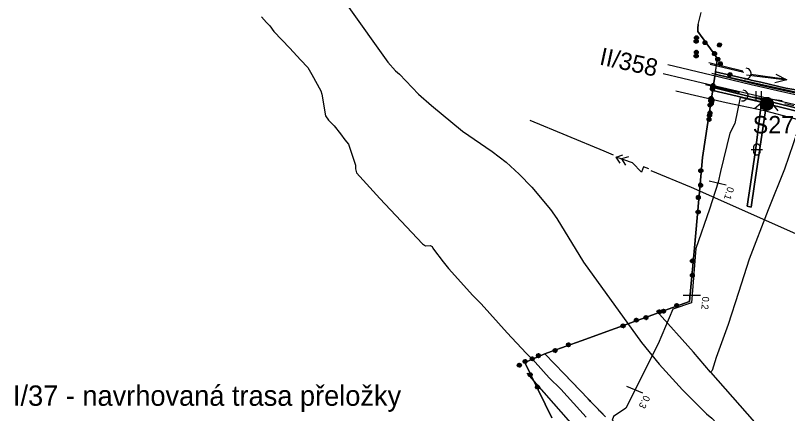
# Model space of a CAD drawing. Extents: x -645676 to -642474, y -1077513 to -1072613.
# Drawn here: x -645676 to -645011, y -1074580 to -1074237 of the extents above; entities that cross this region are included whole.
import ezdxf

# ---------------------------------------------------------------- set-up
doc = ezdxf.new("R2010")
doc.units = 0
for name, color, linetype in [('_elezni_n__tra_', 7, 'Continuous'), ('ELEKTRO', 7, 'Continuous'), ('Kanalizace', 7, 'Continuous'), ('KULTURY_STAV', 7, 'Continuous'), ('KULTURY_ZNACKY', 7, 'Continuous'), ('Navrhovan__prvek_PSZ_s_popisem___plo_n_', 7, 'Continuous'), ('OBVOD_PU', 7, 'Continuous'), ('P__kop___st_vaj_c_', 7, 'Continuous'), ('PC_NAVRH', 7, 'Continuous'), ('PC_OBJ_POPIS_NAVRH', 7, 'Continuous'), ('PC_OBJEKTY_NAVRH', 7, 'Continuous'), ('PC_STAN_NAVRH', 7, 'Continuous'), ('PLYNOVOD', 7, 'Continuous'), ('Popis_silnice_II__a_III__t__dy', 7, 'Continuous'), ('SDELOVACI', 7, 'Continuous'), ('Silnice_II__t__dy_a_III__t__dy', 7, 'Continuous'), ('SPRAV_HR_STAV', 7, 'Continuous'), ('VODOVOD', 7, 'Continuous'), ('VRSTEVNICE', 7, 'Continuous')]:
    doc.layers.add(name, color=color, linetype=linetype)

# ---------------------------------------------------------------- blocks, each defined once
blk = doc.blocks.new('$406')
blk.add_lwpolyline([(-0.19, 0.72), (0.2, 0.72), (0.54, 0.53), (0.73, 0.19), (0.73, -0.2), (0.54, -0.54), (0.2, -0.73), (-0.19, -0.73), (-0.53, -0.54), (-0.72, -0.2), (-0.72, 0.19), (-0.53, 0.53), (-0.2, 0.72), (-0.28, 0.64), (0.28, 0.64), (0.44, 0.56), (-0.44, 0.56), (-0.52, 0.48), (0.52, 0.48), (0.56, 0.4), (-0.55, 0.4), (-0.6, 0.32), (0.6, 0.32), (0.68, 0.24), (-0.59, 0.24), (-0.65, 0.24), (-0.68, 0.16), (0.59, 0.16), (0.68, 0.16), (0.68, 0.08), (-0.59, 0.08), (-0.68, 0.08), (-0.68, 0), (0.59, 0), (0.68, 0), (0.68, -0.08), (-0.59, -0.08), (-0.68, -0.08), (-0.68, -0.16), (0.59, -0.16), (0.68, -0.16), (0.65, -0.24), (-0.62, -0.24), (-0.65, -0.24), (-0.6, -0.32), (0.6, -0.32), (0.56, -0.4), (-0.55, -0.4), (-0.52, -0.48), (0.52, -0.48), (0.44, -0.56), (-0.44, -0.56), (-0.28, -0.64), (0.28, -0.64), (-0.02, -0.69)])
blk = doc.blocks.new('$944')
blk.add_line((0, 1.5), (0, -1.5))
blk = doc.blocks.new('3$0600')
for p, q in [((-0.5, 1.5), (-0.5, 0)), ((0.5, 0), (0.5, 1.5))]:
    blk.add_line(p, q)
blk = doc.blocks.new('3$1600')
for points in [[(-0.5, 1.5), (-0.4, 1.79), (-0.15, 1.97), (0.16, 1.97), (0.41, 1.79), (0.51, 1.5), (0.51, 0.5), (0.41, 0.21), (0.16, 0.03), (-0.15, 0.03), (-0.4, 0.21), (-0.5, 0.5), (-0.5, 1.5)], [(-1, 1), (0.27, 1), (1, 1)]]:
    blk.add_lwpolyline(points)
blk = doc.blocks.new('$935')
blk.add_lwpolyline([(-2, -1), (-1, 0), (1, 0), (2, -1)])
blk = doc.blocks.new('6$1520')
blk.add_line((-3.5, 0), (3.5, 0))
blk.add_lwpolyline([(1.5, 0.75), (3.5, 0), (1.5, -0.75)])
blk = doc.blocks.new('6$2320')
for points in [[(-3.48, 1), (-3.08, 0.92), (-2.68, 0.6), (-2.53, 0.22), (-2.52, -0.2), (-2.72, -0.62), (-3.08, -0.92), (-3.48, -1)], [(-2.53, 0), (-1.26, 0), (0.01, 0), (1.28, 0), (2.55, 0), (3.5, 0)]]:
    blk.add_lwpolyline(points)
blk = doc.blocks.new('6$6120')
for points in [[(-3, 0), (-2, 0), (-2, 1), (0, 0), (3, 0)], [(1, -0.75), (2, 0), (1, 0.75)], [(2, 0.75), (3, 0), (2, -0.75)]]:
    blk.add_lwpolyline(points)
blk = doc.blocks.new('2$0620')
for points in [[(-1.07, 0.32), (-0.88, 0.13), (-0.88, -0.14), (-1.07, -0.33), (-1.34, -0.33), (-1.53, -0.14), (-1.53, 0.13), (-1.34, 0.32), (-1.07, 0.32), (-1.08, 0.28), (-1.32, 0.28), (-1.4, 0.2), (-1, 0.2), (-0.92, 0.12), (-1.48, 0.12), (-1.48, 0.04), (-0.92, 0.04), (-0.92, -0.04), (-1.48, -0.04), (-1.48, -0.12), (-0.92, -0.12), (-1, -0.2), (-1.4, -0.2), (-1.32, -0.28), (-1.08, -0.28)], [(1.43, 0.32), (1.62, 0.13), (1.62, -0.14), (1.43, -0.33), (1.16, -0.33), (0.97, -0.14), (0.97, 0.13), (1.16, 0.32), (1.43, 0.32), (1.4, 0.28), (1.16, 0.28), (1.08, 0.2), (1.48, 0.2), (1.56, 0.12), (1, 0.12), (1, 0.04), (1.56, 0.04), (1.56, -0.04), (1, -0.04), (1, -0.12), (1.56, -0.12), (1.48, -0.2), (1.08, -0.2), (1.16, -0.28), (1.4, -0.28)]]:
    blk.add_lwpolyline(points)

msp = doc.modelspace()

# ---------------------------------------------------------------- linework, layer by layer
at = {"layer": '_elezni_n__tra_'}
msp.add_lwpolyline([(-645235.08, -1074545.28), (-645197.64, -1074588.18), (-645144.91, -1074643.37), (-645108.84, -1074676.16), (-645081.24, -1074696.11), (-645055.83, -1074709.77), (-645032.05, -1074719.88), (-645007.73, -1074729.17)], dxfattribs=at)
at = {"layer": 'ELEKTRO'}
for points in [[(-645160.45, -1074357.6), (-645168.48, -1074354.27), (-645232.33, -1074327.7)], [(-644983.04, -1074434.45), (-645093.47, -1074385.34), (-645128.12, -1074370.99)]]:
    msp.add_lwpolyline(points, dxfattribs=at)
at = {"layer": 'Kanalizace'}
for p, q in [((-645078.51, -1074277.85), (-645049.35, -1074284.91)), ((-645081.26, -1074296.88), (-645052.07, -1074303.8)), ((-645013.14, -1074313.02), (-645005.28, -1074314.88))]:
    msp.add_line(p, q, dxfattribs=at)
at = {"layer": 'KULTURY_STAV'}
for points in [[(-644986.12, -1074304.12), (-645012.27, -1074299.94), (-645033.72, -1074294.88), (-645040.78, -1074293.21), (-645047.35, -1074291.72), (-645049.01, -1074291.35), (-645072.67, -1074285.99), (-645070.95, -1074274.72), (-645074.89, -1074269.28), (-645088.1, -1074251.04), (-645087.86, -1074248.27), (-645087.59, -1074245.2), (-645084.99, -1074234.72)], [(-644995.74, -1074318.77), (-645028.33, -1074310.93), (-645032.03, -1074309.99), (-645074.71, -1074299.47), (-645074.41, -1074297.47), (-645073.19, -1074289.49), (-645072.93, -1074287.76), (-645034.15, -1074297.33), (-644961.13, -1074313.43)], [(-644961.13, -1074313.43), (-645034.15, -1074297.33), (-645072.93, -1074287.76), (-645072.73, -1074286.41), (-645072.67, -1074285.99), (-645049.01, -1074291.35), (-645047.35, -1074291.72), (-645040.78, -1074293.21), (-645033.72, -1074294.88), (-645012.27, -1074299.94), (-644986.12, -1074304.12)], [(-645167.5, -1074582.84), (-645180.27, -1074569.74), (-645182.41, -1074567.34), (-645203.09, -1074546), (-645219.8, -1074528.75), (-645214.32, -1074526.76), (-645188.46, -1074517.37), (-645129.99, -1074496.14), (-645110.24, -1074488.97), (-645095.2, -1074483.51), (-645090.97, -1074437.29), (-645085.97, -1074382.71), (-645083.85, -1074359.6), (-645075.27, -1074303.13), (-645075.09, -1074301.95)], [(-645074.71, -1074299.47), (-645032.03, -1074309.99), (-645028.33, -1074310.93), (-644995.74, -1074318.77), (-644995.88, -1074320.46), (-644995.95, -1074321.35), (-645028.69, -1074313.52), (-645028.93, -1074313.46), (-645031.56, -1074312.33), (-645032.31, -1074312.16), (-645032.29, -1074312.02), (-645033.1, -1074311.67), (-645075.09, -1074301.95), (-645074.71, -1074299.47)], [(-645075.09, -1074301.95), (-645033.1, -1074311.67), (-645033.14, -1074311.99), (-645037.88, -1074351.49), (-645042.65, -1074382.58), (-645045.56, -1074401.52), (-645042.15, -1074402.28), (-645039.21, -1074382.57), (-645038.68, -1074379), (-645034.63, -1074351.79), (-645028.93, -1074313.46), (-645028.69, -1074313.52), (-644995.95, -1074321.35)], [(-645033.1, -1074311.67), (-645032.29, -1074312.02), (-645032.31, -1074312.16), (-645031.56, -1074312.33), (-645028.93, -1074313.46), (-645034.63, -1074351.79), (-645038.68, -1074379), (-645039.21, -1074382.57), (-645042.15, -1074402.28), (-645045.56, -1074401.52), (-645042.65, -1074382.58), (-645037.88, -1074351.49), (-645033.14, -1074311.99), (-645033.1, -1074311.67)], [(-645214.53, -1074581.81), (-645219.61, -1074571.5), (-645237.03, -1074536.14), (-645219.8, -1074528.75), (-645203.09, -1074546), (-645196.75, -1074552.55), (-645182.41, -1074567.34), (-645181.38, -1074568.49), (-645181.1, -1074568.81), (-645180.33, -1074569.68), (-645180.27, -1074569.74), (-645178.82, -1074571.23), (-645176.48, -1074573.63), (-645174.59, -1074575.57), (-645174.5, -1074575.66), (-645173.61, -1074576.57), (-645173.08, -1074577.11), (-645172.08, -1074578.15), (-645170.72, -1074579.54), (-645170.17, -1074580.1), (-645169.59, -1074580.69)]]:
    msp.add_lwpolyline(points, dxfattribs=at)
at = {"layer": 'OBVOD_PU'}
msp.add_lwpolyline([(-645213.55, -1074583.81), (-645237.03, -1074536.14), (-645219.8, -1074528.75), (-645214.32, -1074526.76), (-645188.46, -1074517.37), (-645129.99, -1074496.14), (-645110.24, -1074488.97), (-645095.2, -1074483.51), (-645090.97, -1074437.29), (-645085.97, -1074382.71), (-645083.85, -1074359.6), (-645075.27, -1074303.13), (-645074.71, -1074299.47), (-645074.41, -1074297.47), (-645073.19, -1074289.49), (-645072.93, -1074287.76), (-645072.73, -1074286.41), (-645070.95, -1074274.72), (-645074.89, -1074269.28), (-645088.1, -1074251.04), (-645087.86, -1074248.27), (-645087.59, -1074245.2), (-645084.99, -1074234.72)], dxfattribs=at)
at = {"layer": 'P__kop___st_vaj_c_'}
msp.add_lwpolyline([(-644986.8, -1074307.2), (-645012.67, -1074301.27), (-645041.4, -1074294.92), (-645075.99, -1074287.23)], dxfattribs=at)
at = {"layer": 'PC_NAVRH'}
msp.add_lwpolyline([(-645028.6, -1074313.3), (-645051.47, -1074307.95), (-645056.17, -1074330.34), (-645060.55, -1074338.62), (-645068.58, -1074371.56), (-645070.52, -1074380.73), (-645077.99, -1074404.26), (-645089.66, -1074438.01), (-645093.56, -1074484.75), (-645109.45, -1074490.27), (-645122.18, -1074520.21), (-645150.1, -1074575.63), (-645160.63, -1074582.8), (-645161.83, -1074585.84), (-645149.45, -1074600.95), (-645132.83, -1074618.98), (-645105.79, -1074636.8), (-645104.27, -1074638.65), (-645106.22, -1074659.84), (-645104.92, -1074661.36), (-645087.11, -1074675.92), (-645054.74, -1074695.91), (-645041.17, -1074703.3), (-645022.27, -1074711.12)], dxfattribs=at)
at = {"layer": 'PLYNOVOD'}
for p, q in [((-645002.24, -1074337), (-645013.36, -1074369.64)), ((-645013.36, -1074369.64), (-645027.5, -1074404.76)), ((-645027.5, -1074404.76), (-645043.64, -1074447.2)), ((-645043.64, -1074447.2), (-645052.87, -1074476)), ((-645052.87, -1074476), (-645061.87, -1074503.33)), ((-645091.82, -1074527.23), (-645123.57, -1074491.54)), ((-645061.87, -1074503.33), (-645072.18, -1074531.85)), ((-645077.11, -1074544.54), (-645091.82, -1074527.23)), ((-645072.18, -1074531.85), (-645075.6, -1074543.12)), ((-645075.6, -1074543.12), (-645076.54, -1074544.01)), ((-645076.54, -1074544.01), (-645077.11, -1074544.54)), ((-645077.11, -1074544.54), (-645039.18, -1074587.45))]:
    msp.add_line(p, q, dxfattribs=at)
for points in [[(-644998.47, -1074320.23), (-645002.24, -1074337), (-645013.36, -1074369.64), (-645027.5, -1074404.76), (-645043.64, -1074447.2), (-645052.87, -1074476), (-645061.87, -1074503.33), (-645072.18, -1074531.85), (-645075.6, -1074543.12), (-645077.11, -1074544.54)], [(-645077.11, -1074544.54), (-645091.82, -1074527.23), (-645123.57, -1074491.54)]]:
    msp.add_lwpolyline(points, dxfattribs=at)
at = {"layer": 'SDELOVACI'}
for points in [[(-645463.72, -1074238.57), (-645459.43, -1074243.32), (-645456.45, -1074246.14), (-645453.14, -1074251.11), (-645439.38, -1074265.49), (-645430.01, -1074275.49), (-645423.66, -1074282.13), (-645420.27, -1074288.07), (-645412.69, -1074302.34), (-645411.84, -1074304.99), (-645408.54, -1074323.72), (-645406.13, -1074327.56), (-645401.03, -1074332.39), (-645395.78, -1074339.17), (-645391.93, -1074344.54), (-645388.76, -1074348.03), (-645382.65, -1074366.35), (-645382.7, -1074369.42), (-645381.77, -1074372.94), (-645361.66, -1074394.99), (-645324.99, -1074434.09), (-645322.4, -1074435.59), (-645318.58, -1074435.46), (-645316.86, -1074436.27), (-645316.01, -1074437.72), (-645315.57, -1074438.64), (-645307.25, -1074449.57), (-645302.76, -1074455.35), (-645281.76, -1074478.33), (-645276.04, -1074484.1), (-645274.54, -1074485.57), (-645252.23, -1074510.55), (-645235.84, -1074528.26), (-645227.95, -1074535.91), (-645215.9, -1074549.26), (-645205.85, -1074559.22), (-645184.23, -1074583.12)], [(-644917.54, -1074335.51), (-644920.79, -1074334.28), (-644942.78, -1074329.06), (-644960.69, -1074324.52), (-644969.12, -1074323.02), (-644972.77, -1074321.88), (-644976.39, -1074321.07), (-644977.23, -1074321.34), (-644978.21, -1074321.73), (-644985.72, -1074320.19), (-644992.35, -1074318.89), (-644996.26, -1074318.87), (-644999.59, -1074324.69), (-645001.02, -1074327.49), (-645004.48, -1074326.44), (-645030.69, -1074319.56), (-645063.51, -1074312.42), (-645106.85, -1074302.43)]]:
    msp.add_lwpolyline(points, dxfattribs=at)
at = {"layer": 'Silnice_II__t__dy_a_III__t__dy'}
for p, q in [((-645113.75, -1074279.65), (-645076.47, -1074288.51)), ((-645117.86, -1074287.38), (-645083.97, -1074295.29)), ((-645076.47, -1074288.51), (-645041.9, -1074296.71)), ((-645083.97, -1074295.29), (-645032.3, -1074307.32)), ((-645041.9, -1074296.71), (-645013.18, -1074303.35)), ((-645013.18, -1074303.35), (-644986.96, -1074309.3)), ((-645032.3, -1074307.32), (-644995.53, -1074315.87))]:
    msp.add_line(p, q, dxfattribs=at)
at = {"layer": 'SPRAV_HR_STAV'}
for p, q in [((-645087.59, -1074245.2), (-645084.99, -1074234.72)), ((-645087.86, -1074248.27), (-645088.1, -1074251.04)), ((-645088.1, -1074251.04), (-645074.89, -1074269.28)), ((-645087.59, -1074245.2), (-645087.86, -1074248.27)), ((-645074.89, -1074269.28), (-645070.95, -1074274.72)), ((-645072.73, -1074286.41), (-645070.95, -1074274.72)), ((-645073.19, -1074289.49), (-645074.41, -1074297.47)), ((-645072.93, -1074287.76), (-645073.19, -1074289.49)), ((-645072.73, -1074286.41), (-645072.93, -1074287.76)), ((-645074.41, -1074297.47), (-645074.71, -1074299.47)), ((-645075.27, -1074303.13), (-645083.85, -1074359.6)), ((-645074.71, -1074299.47), (-645075.27, -1074303.13)), ((-645083.85, -1074359.6), (-645085.97, -1074382.71)), ((-645085.97, -1074382.71), (-645090.97, -1074437.29)), ((-645090.97, -1074437.29), (-645095.2, -1074483.51)), ((-645095.2, -1074483.51), (-645110.24, -1074488.97)), ((-645110.24, -1074488.97), (-645129.99, -1074496.14)), ((-645129.99, -1074496.14), (-645188.46, -1074517.37)), ((-645188.46, -1074517.37), (-645214.32, -1074526.76)), ((-645219.8, -1074528.75), (-645237.03, -1074536.14)), ((-645214.32, -1074526.76), (-645219.8, -1074528.75)), ((-645237.03, -1074536.14), (-645213.55, -1074583.81))]:
    msp.add_line(p, q, dxfattribs=at)
at = {"layer": 'VODOVOD'}
msp.add_line((-645077.47, -1074279.29), (-645048.25, -1074286.08), dxfattribs=at)
at = {"layer": 'VRSTEVNICE'}
msp.add_lwpolyline([(-645389.8, -1074228.48), (-645354.76, -1074277.47), (-645348.35, -1074284.88), (-645344.79, -1074287.87), (-645328.56, -1074304.96), (-645317.3, -1074314.93), (-645290.53, -1074336.86), (-645265.04, -1074354.52), (-645252.93, -1074363.78), (-645241.68, -1074374.03), (-645231, -1074385.28), (-645214.9, -1074404.51), (-645209.49, -1074412.06), (-645186.51, -1074449.7), (-645136.57, -1074518.88), (-645121.19, -1074537.53), (-645101.25, -1074559.75), (-645080.46, -1074580.4), (-645075.9, -1074583.96), (-645051.97, -1074609.6), (-645037.73, -1074629.68), (-645027.05, -1074648.91), (-645009.67, -1074694.48)], dxfattribs=at)

# ---------------------------------------------------------------- block references
at = {"layer": 'ELEKTRO', "xscale": 5.000000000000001, "yscale": 5, "rotation": 160.249279}
msp.add_blockref('6$6120', (-645144.29, -1074364.29), dxfattribs=at)
at = {"layer": 'Kanalizace', "xscale": 5, "yscale": 5.000000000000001}
for p, rotation in [((-645029.91, -1074289.61), -7.555948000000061), ((-645032.6, -1074308.41), -7.277527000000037)]:
    msp.add_blockref('6$2320', p, dxfattribs=dict(at, rotation=rotation))
at = {"layer": 'KULTURY_ZNACKY', "xscale": 5, "yscale": 5}
for name, p in [('3$0600', (-645035.55, -1074310.15)), ('3$1600', (-645037.18, -1074357.77))]:
    msp.add_blockref(name, p, dxfattribs=at)
at = {"layer": 'PC_OBJEKTY_NAVRH', "xscale": 5, "yscale": 5, "rotation": -5.619957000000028}
msp.add_blockref('$935', (-645028.64, -1074313.35), dxfattribs=at)
at = {"layer": 'PC_STAN_NAVRH', "xscale": 7.5, "yscale": 7.5}
msp.add_blockref('$406', (-645028.6, -1074313.3), dxfattribs=at)
at = {"layer": 'PC_STAN_NAVRH', "xscale": 5}
for p, yscale, rotation in [((-645070.82, -1074381.67), 5, -103.18959400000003), ((-645093.03, -1074478.46), 5, -90.13134100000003), ((-645142.12, -1074559.79), 5.000000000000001, -112.481941)]:
    msp.add_blockref('$944', p, dxfattribs=dict(at, yscale=yscale, rotation=rotation))
at = {"layer": 'SPRAV_HR_STAV'}
for p, xscale, yscale, rotation in [((-645089.12, -1074262.63), 5.000000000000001, 5, -90.40145000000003), ((-645089.37, -1074265.7), 5.000000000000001, 5.000000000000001, -90.325924), ((-645077.84, -1074265.21), 5, 5, -48.74753400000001), ((-645070.1, -1074269.11), 5, 5, 82.761943), ((-645064.62, -1074283.45), 5, 5, -48.74628300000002), ((-645075.53, -1074305.07), 5, 5.000000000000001, -93.983754), ((-645075.29, -1074303.72), 5, 4.999999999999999, -93.86166700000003), ((-645075.83, -1074306.79), 5, 5, -94.131526), ((-645077.36, -1074316.77), 5, 5.000000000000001, -94.13853100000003), ((-645077.01, -1074314.78), 5, 4.999999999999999, -93.96726999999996), ((-645077.9, -1074320.43), 5, 4.999999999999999, -94.07779300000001), ((-645085.45, -1074377.03), 5, 5.000000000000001, -90.62046799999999), ((-645087.57, -1074400.14), 5, 5, -90.61315700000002), ((-645092.56, -1074454.72), 5.000000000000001, 5, -90.60795900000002), ((-645126.69, -1074494.94), 5, 4.999999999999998, -156.557347), ((-645111.65, -1074489.48), 5, 5.000000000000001, -156.557653), ((-645146.44, -1074502.11), 4.999999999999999, 5.000000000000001, -156.554553), ((-645204.91, -1074523.34), 5.000000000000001, 5, -156.553678), ((-645230.77, -1074532.73), 5.000000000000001, 5, -156.55216300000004), ((-645235.88, -1074535.65), 5, 5, -153.238592), ((-645229.3, -1074551.84), 5.000000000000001, 4.999999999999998, -58.60725700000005)]:
    msp.add_blockref('2$0620', p, dxfattribs=dict(at, xscale=xscale, yscale=yscale, rotation=rotation))
at = {"layer": 'VODOVOD', "xscale": 5, "yscale": 5, "rotation": -7.034326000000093}
msp.add_blockref('6$1520', (-645028.77, -1074290.61), dxfattribs=at)

# ---------------------------------------------------------------- texts
at = {"layer": 'Navrhovan__prvek_PSZ_s_popisem___plo_n_'}
msp.add_text('I/37 - navrhovaná trasa přeložky ', height=17.5, dxfattribs=at).set_placement((-645677.72, -1074573.44))
at = {"layer": 'PC_OBJ_POPIS_NAVRH'}
msp.add_text('S27', height=15, dxfattribs=at).set_placement((-645040.7, -1074338.87))
at = {"layer": 'PC_STAN_NAVRH'}
for s, rotation, p in [('0.1', 252.388, (-645062.24, -1074384.38)), ('0.2', 265.222, (-645084.06, -1074479.2)), ('0.3', 243.278, (-645134.08, -1074563.84))]:
    msp.add_text(s, height=6, rotation=rotation, dxfattribs=at).set_placement(p)
at = {"layer": 'Popis_silnice_II__a_III__t__dy'}
msp.add_text('II/358', height=15, rotation=347.624, dxfattribs=at).set_placement((-645173.4, -1074279.39))

doc.saveas('drawing.dxf')
